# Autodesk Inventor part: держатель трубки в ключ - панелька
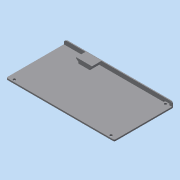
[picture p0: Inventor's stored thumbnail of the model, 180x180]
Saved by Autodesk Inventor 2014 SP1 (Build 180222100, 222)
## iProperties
Created: 2015-10
Part Number: держатель трубки в ключ - панелька
Material: Типовые
Document SubType Name: Modeling
Designer: hals
Density: 1 g/cm^3
Appearance: По умолчанию
Author: hals
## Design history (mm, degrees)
sketch "Эскиз1"
  geometry: L1 (8.5, -1.7)-(-8.5, -1.7); L2 (-11, 0.3)-(-11, 1.7); L3 (-11, 1.7)-(11, 1.7); L4 (11, 1.7)-(11, 0.3); L5 (11, -1.7)-(-11, 1.7); L6 (-11, -1.7)-(11, 1.7); L7 (-8, -4.338)-(8, -4.338); L8 (8, -4.338)-(8, -2.34); L9 (8, -1.7)-(-8, -1.7); L10 (-8, -2.34)-(-8, -4.338); L11 (-8, -4.338)-(8, -1.7); L12 (8, -4.338)-(-8, -1.7); L13 (0, 0)-(0, -10.525); L14 (-11, 0.3)-(-8.188, -1.95); L15 (8.188, -1.95)-(11, 0.3); A1 r 0.5 centre (-8.5, -2.34) between (-8, -2.34) and (-8.188, -1.95); A2 r 0.5 centre (8.5, -2.34) between (8.188, -1.95) and (8, -2.34); 3 further points
  constraints: 30 end point, 10 point on line, 6 midpoint, 5 parallel, 4 point on circle, 4 tangent, 2 centre point, 2 horizontal, 2 perpendicular, 1 collinear, 1 equal radius
  dimensions: "d0" = 22 distance of L2.end L3.end; "d1" = 3.4 distance of L6.start L2.end; "d2" = 16 distance of L7.start L7.end; "d3" = 2.6383 distance of L7.end L9.start; "d14" = 2 distance of L2.start L6.start; "d15" = 2.5 distance of L1.end L6.start; "d16" = 2.5 distance of L1.start L5.start; "d17" = 2 distance of L4.end L5.start; "d18" = 0.5 radius of A1
extrude "Выдавливание1" new body sketch "Эскиз1" distance "d4" = 13; taper "d5" = 0 deg
sketch "Эскиз2"
  geometry: L1 (8, 4.338)-(-8, 4.338) reference; L2 (-8.65, 1.7)-(-11, 1.7) reference; L3 (-11, -0.3)-(-11, -1.7) reference; L4 (-11, -1.7)-(11, -1.7) reference; L5 (11, -1.7)-(11, -0.3) reference; L6 (11, 1.7)-(8.65, 1.7) reference; L7 (-11, -1.7)-(-41, -1.7); L8 (-41, -1.7)-(-41, 6.338); L9 (-41, 6.338)-(109, 6.338); L10 (109, 6.338)-(109, -1.7); L11 (109, -1.7)-(11, -1.7); 3 further points; 2 other entities
  constraints: 10 end point, 2 parallel, 2 perpendicular, 1 horizontal, 2 other
  dimensions: "d6" = 2 distance between parallel lines of L9 L1; "d7" = 150 distance of L8.end L9.end; "d8" = 30 distance between parallel lines of L3 L8
extrude "Выдавливание2" join sketch "Эскиз2" distance "d9" = 2.5; taper "d10" = 0 deg
sketch "Эскиз3"
  geometry: L1 (109, 1.7)-(109, -6.338) reference; L2 (-41, -6.338)-(109, -6.338); L3 (109, -6.338)-(109, -4.338); L4 (109, -4.338)-(-41, -4.338); L5 (-41, -4.338)-(-41, -6.338); 1 further point
  constraints: 8 end point, 2 parallel, 1 horizontal, 1 perpendicular, 1 point on line
  dimensions: "d11" = 2 distance of L2.end L3.end
extrude "Выдавливание3" join sketch "Эскиз3" distance "d12" = 80; taper "d13" = 0 deg
fillet "Сопряжение1" dims "d19" = 4
fillet "Сопряжение2" dims "d20" = 2
fillet "Сопряжение3" dims "d21" = 2
node "Отверстие3"
node "Отверстие5"
node "Отверстие7"
sketch "Эскиз8"
  geometry: L1 (8, -4.338)-(99.625, -4.338) reference; L2 (97.65, -4.338)-(104.02, -4.338); L3 (104.02, -4.338)-(104.02, -2.3); L4 (104.02, -2.3)-(97.65, -2.3); L5 (97.65, -2.3)-(97.65, -4.338); 1 further point
  constraints: 8 end point, 2 parallel, 1 horizontal, 1 perpendicular, 1 point on line
extrude "Выдавливание4" cut sketch "Эскиз8" distance "d50" = 2; taper "d51" = 0 deg
fillet "Сопряжение4" dims "d52" = 0.5
fillet "Сопряжение5" dims "d53" = 2
sketch "Эскиз9"
  geometry: L1 (148, -80.5)-(148, -2) reference; L2 (0, 0)-(146, 0) reference; L3 (-2, -80.5)-(-2, -2) reference; L4 (146, -82.5)-(0, -82.5) reference; C1 r 1.7 at (6, -3.5) reference; C2 r 1.7 at (140.131, -78.959) reference; C3 r 1.7 at (6, -78.959) reference; A1 r 2 centre (146, -80.5) between (146, -82.5) and (148, -80.5) reference; A2 r 2 centre (146, -2) between (148, -2) and (146, 0) reference; A3 r 2 centre (0, -2) between (0, 0) and (-2, -2) reference; A4 r 2 centre (0, -80.5) between (-2, -80.5) and (0, -82.5) reference; 1 further point
node "Твердое тело1"
sketch "Эскиз5"
  geometry: 1 further point
hole "Отверстие2" sketch "Эскиз5" diameter "d29" = 3.4; stored, may be unused: countersink angle "d33" = 90 deg, drill point angle "d35" = 0 deg; dims "d30" = 6, "d31" = 4, "d32" = 2, "d34" = 8
sketch "Эскиз6"
  geometry: 1 further point
hole "Отверстие4" sketch "Эскиз6" diameter "d36" = 3.4; stored, may be unused: countersink angle "d40" = 90 deg, drill point angle "d42" = 0 deg; dims "d37" = 6, "d38" = 4, "d39" = 2, "d41" = 8
sketch "Эскиз7"
  geometry: 1 further point
hole "Отверстие6" sketch "Эскиз7" diameter "d43" = 3.4; stored, may be unused: countersink angle "d47" = 90 deg, drill point angle "d49" = 0 deg; dims "d44" = 6, "d45" = 4, "d46" = 2, "d48" = 8
